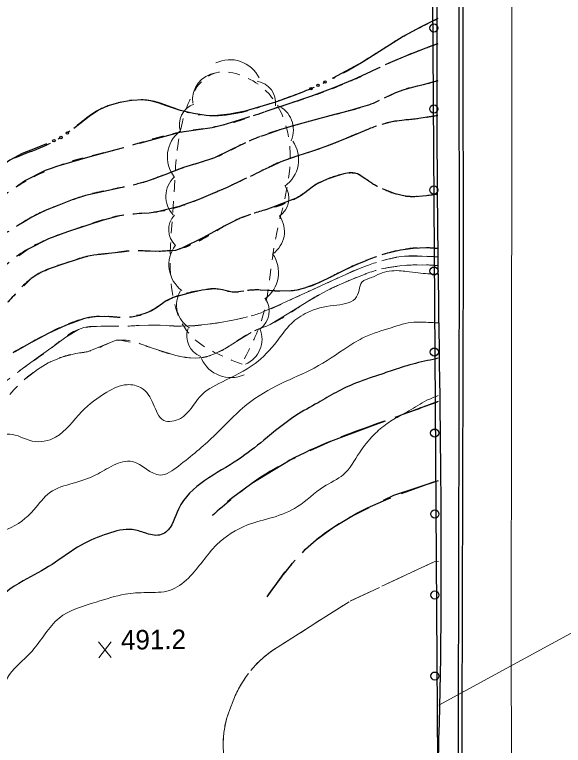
# Model space of a CAD drawing. Extents: x 2362213 to 2366494, y 6968794 to 6978110.
# Drawn here: x 2364260.3 to 2364395.9, y 6970244.9 to 6970425.3 of the extents above; entities that cross this region are included whole.
import ezdxf

# ---------------------------------------------------------------- set-up
doc = ezdxf.new("R2010")
doc.units = 0
doc.header["$LTSCALE"] = 1.9
for name, pattern in [('DASH_DOUBLE_DOT', [9.2, 5, -1.2, 0.3, -1.2, 0.3, -1.2]), ('LONG_DASHED', [7.5, 6, -1.5]), ('MEDIUM_DASHED', [4.5, 3, -1.5]), ('SHORT_DASHED', [2.7, 1.5, -1.2])]:
    doc.linetypes.add(name, pattern=pattern)
for name, color, linetype, lineweight in [('2', 7, 'Continuous', 25), ('25', 7, 'Continuous', 25), ('29', 7, 'Continuous', 13), ('3', 7, 'Continuous', 25), ('31', 7, 'Continuous', 25), ('32', 7, 'Continuous', 25), ('35', 7, 'Continuous', 13), ('36', 7, 'Continuous', 13), ('4', 7, 'Continuous', 25), ('62', 7, 'Continuous', 13), ('8', 7, 'Continuous', 13), ('9', 7, 'Continuous', 13)]:
    doc.layers.add(name, color=color, linetype=linetype, lineweight=lineweight)

msp = doc.modelspace()

# ---------------------------------------------------------------- linework, layer by layer
at = {"layer": '2'}
msp.add_line((2364369.912, 6970250.572), (2364369.913, 6970250.559), dxfattribs=at)
for points in [[(2364369.913, 6970250.559), (2364370.193, 6970367.087), (2364369.986, 6970514.833), (2364369.855, 6970701.89), (2364369.323, 6970871.152), (2364368.954, 6970929.733), (2364368.956, 6970929.692)], [(2364370.872, 6970250.558), (2364371.153, 6970367.086), (2364370.946, 6970514.832), (2364370.815, 6970701.889), (2364370.282, 6970871.162), (2364369.914, 6970929.742), (2364369.914, 6970929.741)]]:
    msp.add_lwpolyline(points, dxfattribs=at)
for centre, radius, start, end in [((2348841.903, 6970149.815), 15528.336, 0.23277, 0.37177), ((2348832.824, 6970339.444), 15538.302, 359.53334, 359.67224)]:
    msp.add_arc(centre, radius, start, end, dxfattribs=at)
at = {"layer": '25'}
for points in [[(2364364.847, 6970424.35), (2364360.517, 6970422.208), (2364356.278, 6970419.897), (2364351.328, 6970416.799), (2364346.378, 6970413.692), (2364339.98, 6970410.201), (2364338.746, 6970409.599)], [(2364331.637, 6970406.291), (2364329.107, 6970405.267), (2364324.692, 6970403.755), (2364317.212, 6970401.535), (2364313.449, 6970400.759), (2364309.673, 6970400.343), (2364307.582, 6970400.393), (2364304.427, 6970400.903), (2364301.291, 6970401.642), (2364297.578, 6970402.907), (2364295.751, 6970403.57), (2364293.886, 6970404.062), (2364292.004, 6970404.274), (2364289.135, 6970404.157), (2364286.28, 6970403.659), (2364283.667, 6970402.925), (2364282.402, 6970402.422), (2364281.167, 6970401.821), (2364278.674, 6970400.198), (2364275.219, 6970397.444), (2364274.931, 6970397.241)], [(2364268.106, 6970393.466), (2364265.307, 6970392.289), (2364262.099, 6970391.009), (2364259.085, 6970389.39), (2364250.531, 6970383.398), (2364242.191, 6970377.129), (2364233.253, 6970369.623), (2364224.051, 6970362.335), (2364220.43, 6970360.25), (2364218.926, 6970359.646)]]:
    msp.add_lwpolyline(points, dxfattribs=at)
for centre in [(2364335.221, 6970407.892), (2364336.949, 6970408.73), (2364333.494, 6970407.054), (2364271.724, 6970395.004), (2364273.3, 6970396.102), (2364269.965, 6970394.24)]:
    msp.add_circle(centre, 0.3, dxfattribs=at)
at = {"layer": '25', "linetype": 'DASH_DOUBLE_DOT'}
msp.add_spline([(2364364.847, 6970424.35), (2364356.278, 6970419.897), (2364346.378, 6970413.692), (2364333.4, 6970407.008), (2364324.692, 6970403.755), (2364309.673, 6970400.343), (2364301.291, 6970401.642), (2364293.886, 6970404.062), (2364286.28, 6970403.659), (2364281.167, 6970401.821), (2364271.632, 6970394.94), (2364259.085, 6970389.39), (2364242.191, 6970377.129), (2364224.051, 6970362.335), (2364208.66, 6970356.078), (2364195, 6970352.758)], degree=3, dxfattribs=at)
at = {"layer": '29'}
for centre, radius, start, end in [((2364313.464, 6970406.214), 7.997, 25.86205, 115.86205), ((2364310.899, 6970404.35), 6.668, 97.66191, 187.66191), ((2364319.431, 6970403.598), 5.329, 351.41371, 81.41371), ((2364306.313, 6970398.206), 5.329, 108.91941, 198.91941), ((2364322.487, 6970396.867), 6.668, 336.53524, 66.53524), ((2364306.016, 6970390.241), 7.997, 128.05769, 218.05769), ((2364322.439, 6970389.537), 7.997, 304.77131, 34.77131), ((2364304.312, 6970380.451), 6.668, 133.30247, 223.30247), ((2364322.718, 6970379.984), 5.329, 304.71158, 34.71158), ((2364303.66, 6970372.231), 5.329, 137.16086, 227.16086), ((2364320.271, 6970371.783), 6.668, 304.71158, 34.71158), ((2364306.396, 6970363.591), 7.997, 143.11461, 233.11461), ((2364317.488, 6970361.674), 7.997, 305.3686, 35.3686), ((2364306.943, 6970353.678), 6.668, 148.95248, 238.95248), ((2364317.843, 6970352.137), 5.329, 305.18192, 35.18192), ((2364308.128, 6970345.947), 5.329, 159.55382, 249.55382), ((2364314.725, 6970345.178), 6.668, 292.65251, 22.65251), ((2364313.708, 6970343.713), 7.997, 204.51246, 294.51246)]:
    msp.add_arc(centre, radius, start, end, dxfattribs=at)
at = {"layer": '29', "linetype": 'SHORT_DASHED'}
msp.add_spline([(2364316.457, 6970339.004), (2364304.052, 6970345.836), (2364299.605, 6970380.155), (2364300.565, 6970392.825), (2364310.032, 6970410.956), (2364321.135, 6970407.612), (2364328.361, 6970390.12), (2364324.524, 6970368.912), (2364321.255, 6970349.84), (2364316.573, 6970339.455)], degree=3, dxfattribs=at)
at = {"layer": '3'}
msp.add_line((2364309.876, 6970302.35), (2364309.132, 6970301.692), dxfattribs=at)
for points in [[(2364364.938, 6970329.785), (2364361.15, 6970328.399), (2364357.363, 6970327.003), (2364355.549, 6970326.336)], [(2364351.792, 6970324.95), (2364347.827, 6970323.492), (2364338.289, 6970319.971), (2364333.201, 6970317.612)], [(2364329.577, 6970315.928), (2364328.323, 6970315.346), (2364318.877, 6970309.565), (2364313.823, 6970305.847), (2364312.871, 6970305.008)], [(2364351.429, 6970305.425), (2364353.986, 6970306.69), (2364364.983, 6970310.345)], [(2364331.401, 6970292.484), (2364332.173, 6970293.331), (2364334.8, 6970295.697), (2364339.021, 6970298.797), (2364343.566, 6970301.54), (2364347.846, 6970303.651)], [(2364322.645, 6970281.58), (2364327.057, 6970287.701), (2364328.709, 6970289.518)]]:
    msp.add_lwpolyline(points, dxfattribs=at)
at = {"layer": '3', "linetype": 'LONG_DASHED'}
for points in [[(2364364.938, 6970329.785), (2364357.363, 6970327.003), (2364338.289, 6970319.971), (2364318.877, 6970309.565), (2364309.132, 6970301.692)], [(2364322.645, 6970281.58), (2364332.173, 6970293.331), (2364343.566, 6970301.54), (2364364.983, 6970310.345)]]:
    msp.add_spline(points, degree=3, dxfattribs=at)
at = {"layer": '31', "lineweight": 13}
for p, q in [((2364284.125, 6970266.593), (2364281.009, 6970270.443)), ((2364281.046, 6970266.563), (2364284.088, 6970270.473))]:
    msp.add_line(p, q, dxfattribs=at)
at = {"layer": '31'}
msp.add_spline([(2364364.916, 6970340.535), (2364363.708, 6970340.224), (2364360.793, 6970339.586), (2364355.098, 6970337.982), (2364350.983, 6970336.593), (2364344.743, 6970334.403), (2364339.684, 6970332.075), (2364335.238, 6970329.512), (2364329.728, 6970326.32), (2364321.827, 6970320.254), (2364315.571, 6970315.494), (2364307.24, 6970310.284), (2364300.728, 6970303.272), (2364297.611, 6970297.563), (2364296.087, 6970296.848), (2364292.482, 6970297.354), (2364289.344, 6970298.194), (2364283.244, 6970297.156), (2364276.711, 6970294.353), (2364269.505, 6970289.585), (2364262.404, 6970285.546), (2364254.518, 6970278.891), (2364252.946, 6970276.856), (2364250.196, 6970275.81), (2364245.104, 6970269.681), (2364243.153, 6970266.583), (2364239.68, 6970265.898), (2364238.01, 6970263.732), (2364238.482, 6970262.497)], degree=3, dxfattribs=at)
at = {"layer": '32'}
for points in [[(2364364.846, 6970418.158), (2364363.361, 6970417.614), (2364361.886, 6970417.06), (2364357.223, 6970415.206), (2364352.601, 6970413.271), (2364351.865, 6970412.924)], [(2364348.242, 6970411.23), (2364344.1, 6970409.28), (2364338.919, 6970407.141), (2364333.658, 6970405.191), (2364328.005, 6970403.277), (2364322.344, 6970401.404), (2364322.085, 6970401.321)], [(2364364.843, 6970409.028), (2364363.047, 6970408.501), (2364361.252, 6970407.994), (2364358.848, 6970407.401), (2364356.443, 6970406.798), (2364354.371, 6970406.018), (2364351.563, 6970404.721)], [(2364347.919, 6970403.086), (2364345.656, 6970402.365), (2364342.963, 6970401.59), (2364338.114, 6970400.314), (2364333.266, 6970399.038), (2364329.656, 6970398.022), (2364326.057, 6970396.958), (2364321.86, 6970395.518), (2364321.063, 6970395.21)], [(2364318.286, 6970400.075), (2364317.039, 6970399.673), (2364311.715, 6970398.011), (2364309.08, 6970397.426), (2364301.032, 6970396.22), (2364293.79, 6970394.271), (2364291.106, 6970393.545)], [(2364364.846, 6970400.398), (2364362.228, 6970399.983), (2364359.612, 6970399.589), (2364356.545, 6970399.239), (2364353.489, 6970398.86), (2364351.035, 6970398.216)], [(2364347.268, 6970396.88), (2364343.623, 6970395.365), (2364339.737, 6970393.768), (2364336.936, 6970392.721), (2364334.126, 6970391.695), (2364330.038, 6970390.416), (2364326.022, 6970388.987), (2364323.812, 6970387.956), (2364321.602, 6970386.905), (2364321.204, 6970386.721)], [(2364317.356, 6970393.715), (2364313.713, 6970391.92), (2364309.661, 6970390.001), (2364305.833, 6970388.765), (2364301.985, 6970387.558), (2364297.421, 6970385.785), (2364292.816, 6970384.151), (2364291.25, 6970383.746)], [(2364287.246, 6970392.488), (2364286.548, 6970392.301), (2364278.859, 6970390.188), (2364271.188, 6970388.035), (2364267.809, 6970386.843), (2364262.992, 6970384.387), (2364261.055, 6970383.068)], [(2364347.688, 6970384.273), (2364346.652, 6970384.983), (2364345.826, 6970385.556), (2364344.961, 6970386.027), (2364344.38, 6970386.222), (2364343.309, 6970386.322), (2364341.63, 6970386.056), (2364340.005, 6970385.57), (2364337.473, 6970384.676), (2364335.024, 6970383.553), (2364333.761, 6970382.721), (2364331.975, 6970381.314), (2364331.051, 6970380.665), (2364330.066, 6970380.135), (2364326.241, 6970378.589), (2364322.375, 6970377.173), (2364322.365, 6970377.173)], [(2364317.599, 6970384.997), (2364317.181, 6970384.793), (2364312.751, 6970382.691), (2364309.275, 6970381.147), (2364305.749, 6970379.694), (2364300.896, 6970377.998), (2364295.927, 6970376.691), (2364293.51, 6970376.337), (2364291.221, 6970376.215)], [(2364287.359, 6970382.809), (2364286.84, 6970382.684), (2364282.309, 6970381.701), (2364277.789, 6970380.668), (2364274.479, 6970379.596), (2364271.231, 6970378.315), (2364267.813, 6970376.953), (2364264.509, 6970375.341), (2364262.222, 6970373.949), (2364261.208, 6970373.319)], [(2364364.83, 6970380.996), (2364362.013, 6970380.58), (2364359.185, 6970380.383), (2364357.975, 6970380.381), (2364356.754, 6970380.499), (2364354.308, 6970381.066), (2364351.96, 6970381.954), (2364351.186, 6970382.337)], [(2364287.245, 6970375.797), (2364286.216, 6970375.668), (2364282.137, 6970374.559), (2364278.09, 6970373.31), (2364273.334, 6970371.715), (2364268.64, 6970369.94), (2364263.624, 6970367.422), (2364261.269, 6970365.82)], [(2364318.555, 6970375.956), (2364316.034, 6970375.051), (2364314.033, 6970374.082), (2364312.062, 6970373.074), (2364306.908, 6970370.334), (2364301.604, 6970367.654), (2364300.019, 6970367.139), (2364297.551, 6970366.895), (2364295.071, 6970366.871), (2364292.6, 6970366.978)], [(2364288.61, 6970366.95), (2364286.652, 6970366.711), (2364284.255, 6970366.408), (2364282.057, 6970366.178), (2364279.85, 6970365.937), (2364278.023, 6970365.599), (2364272.678, 6970363.918), (2364268.332, 6970362.407), (2364266.271, 6970361.437), (2364264.363, 6970360.169), (2364262.52, 6970358.401)], [(2364364.848, 6970367.576), (2364363.356, 6970367.712), (2364361.875, 6970367.758), (2364358.746, 6970367.628), (2364355.63, 6970367.208), (2364351.859, 6970366.312), (2364351.041, 6970366.034)], [(2364347.285, 6970364.669), (2364344.974, 6970363.697), (2364341.777, 6970362.256), (2364338.631, 6970360.696), (2364335.466, 6970359.136), (2364331.869, 6970357.761), (2364330.003, 6970357.304), (2364328.116, 6970357.056), (2364324.555, 6970357.162), (2364320.994, 6970357.338), (2364320.854, 6970357.337)], [(2364316.865, 6970357.069), (2364316.166, 6970356.962), (2364314.978, 6970356.781), (2364313.657, 6970356.868), (2364311.662, 6970357.349), (2364310.67, 6970357.55), (2364309.679, 6970357.62), (2364308.16, 6970357.506), (2364306.643, 6970357.271), (2364303.031, 6970356.497), (2364299.48, 6970355.473), (2364297.737, 6970354.637), (2364295.323, 6970352.973), (2364294.08, 6970352.191), (2364292.726, 6970351.598), (2364291.13, 6970351.153), (2364290.351, 6970351.016)], [(2364286.385, 6970350.578), (2364286.285, 6970350.567), (2364284.324, 6970350.708), (2364282.363, 6970350.84), (2364279.835, 6970350.706), (2364278.577, 6970350.524), (2364277.319, 6970350.212), (2364272.804, 6970348.589), (2364268.523, 6970346.588), (2364266.423, 6970345.488), (2364264.344, 6970344.358), (2364260.504, 6970342.161), (2364260.345, 6970342.07)]]:
    msp.add_lwpolyline(points, dxfattribs=at)
at = {"layer": '32', "linetype": 'SHORT_DASHED'}
for points in [[(2364364.846, 6970418.158), (2364361.886, 6970417.06), (2364352.601, 6970413.271), (2364344.1, 6970409.28), (2364333.658, 6970405.191), (2364322.344, 6970401.404), (2364311.715, 6970398.011), (2364301.032, 6970396.22), (2364286.548, 6970392.301), (2364271.188, 6970388.035), (2364258.521, 6970381.334), (2364245.947, 6970371.184), (2364239.365, 6970366.191), (2364225.916, 6970358.643), (2364217.01, 6970353.978), (2364202.526, 6970348.039)], [(2364364.843, 6970409.028), (2364361.252, 6970407.994), (2364356.443, 6970406.798), (2364348.318, 6970403.22), (2364342.963, 6970401.59), (2364333.266, 6970399.038), (2364326.057, 6970396.958), (2364317.734, 6970393.899), (2364309.661, 6970390.001), (2364301.985, 6970387.558), (2364292.816, 6970384.151), (2364286.84, 6970382.684), (2364277.789, 6970380.668), (2364271.231, 6970378.315), (2364264.509, 6970375.341), (2364259.955, 6970372.537), (2364255.123, 6970369.681), (2364250.295, 6970366.155), (2364248.152, 6970364.425), (2364245.292, 6970361.247), (2364242.781, 6970358.163), (2364237.11, 6970356.199), (2364232.291, 6970355.093)], [(2364364.846, 6970400.398), (2364359.612, 6970399.589), (2364353.489, 6970398.86), (2364347.507, 6970396.982), (2364339.737, 6970393.768), (2364334.126, 6970391.695), (2364326.022, 6970388.987), (2364321.602, 6970386.905), (2364312.751, 6970382.691), (2364305.749, 6970379.694), (2364295.927, 6970376.691), (2364286.216, 6970375.668), (2364278.09, 6970373.31), (2364268.64, 6970369.94), (2364258.974, 6970364.258), (2364252.648, 6970358.517), (2364248.675, 6970355.709)], [(2364364.83, 6970380.996), (2364359.185, 6970380.383), (2364356.754, 6970380.499), (2364351.96, 6970381.954), (2364348.302, 6970383.859), (2364344.961, 6970386.027), (2364340.005, 6970385.57), (2364335.024, 6970383.553), (2364330.066, 6970380.135), (2364322.375, 6970377.173), (2364316.034, 6970375.051), (2364312.062, 6970373.074), (2364301.604, 6970367.654), (2364295.071, 6970366.871), (2364289.049, 6970367.004), (2364284.255, 6970366.408), (2364279.85, 6970365.937), (2364272.678, 6970363.918), (2364264.363, 6970360.169), (2364258.637, 6970354.444), (2364251.944, 6970348.45), (2364245.525, 6970338.888), (2364243.364, 6970334.818), (2364238.212, 6970332.839), (2364230.715, 6970332.507), (2364221.484, 6970331.538), (2364213.708, 6970331.074), (2364206.141, 6970331.752), (2364197.681, 6970333.823)], [(2364364.848, 6970367.576), (2364361.875, 6970367.758), (2364355.63, 6970367.208), (2364348.211, 6970365.057), (2364341.777, 6970362.256), (2364335.466, 6970359.136), (2364328.116, 6970357.056), (2364320.994, 6970357.338), (2364317.364, 6970357.143), (2364314.978, 6970356.781), (2364309.679, 6970357.62), (2364306.643, 6970357.271), (2364299.48, 6970355.473), (2364292.726, 6970351.598), (2364286.285, 6970350.567), (2364282.363, 6970350.84), (2364277.319, 6970350.212), (2364268.523, 6970346.588), (2364264.344, 6970344.358), (2364256.697, 6970339.895), (2364249.127, 6970333.432), (2364244.461, 6970319.387), (2364241.848, 6970311.192), (2364238.032, 6970310.766), (2364231.618, 6970311.275), (2364224.298, 6970312.255), (2364217.804, 6970313.663), (2364212.629, 6970314.124), (2364205.732, 6970314.848), (2364194.373, 6970316.77), (2364179.745, 6970317.591)]]:
    msp.add_spline(points, degree=3, dxfattribs=at)
at = {"layer": '35'}
for points in [[(2364364.869, 6970361.176), (2364359.954, 6970361.559), (2364357.181, 6970361.893), (2364355.279, 6970362.105), (2364350.507, 6970361.369), (2364348.396, 6970360.399), (2364346.086, 6970359.317), (2364345.395, 6970357.32), (2364344.385, 6970355.202), (2364339.1, 6970353.54), (2364332.596, 6970351.778), (2364328.642, 6970349.06), (2364325.045, 6970344.656), (2364319.665, 6970339.174), (2364311.429, 6970334.616), (2364306.043, 6970331.004), (2364301.225, 6970325.638), (2364297.098, 6970325.159), (2364294.529, 6970329.245), (2364291.561, 6970333.177), (2364288.074, 6970333.963), (2364283.071, 6970332.115), (2364276.847, 6970327.316), (2364270.386, 6970320.994), (2364264.575, 6970320.049), (2364259.068, 6970321.777), (2364252.806, 6970317.847), (2364249.725, 6970305.317), (2364244.346, 6970297.805), (2364233.011, 6970296.287), (2364222.955, 6970294.682), (2364211.465, 6970293.652), (2364200.277, 6970293.315), (2364191.374, 6970294.591), (2364180.631, 6970295.909)], [(2364364.893, 6970349.256), (2364362.421, 6970349.352), (2364358.94, 6970349.399), (2364353.293, 6970348.035), (2364346.666, 6970345.682), (2364342.618, 6970343.323), (2364334.287, 6970338.074), (2364326.104, 6970334.246), (2364317.672, 6970329.075), (2364309.426, 6970321.206), (2364300.746, 6970313.883), (2364296.247, 6970311.64), (2364289.365, 6970314.975), (2364284.673, 6970314.06), (2364280.337, 6970311.669), (2364274.695, 6970309.634), (2364268.976, 6970307.33), (2364265.027, 6970303.043), (2364258.533, 6970298.32), (2364254.035, 6970297.018), (2364249.354, 6970294.883), (2364244.948, 6970291.271), (2364241.093, 6970286.533), (2364238.443, 6970282.378), (2364234.948, 6970279.815), (2364230.3, 6970282.591), (2364224.36, 6970285.753), (2364217.545, 6970284.15), (2364212.757, 6970278.634), (2364208.692, 6970274.915), (2364198.732, 6970273.87), (2364192.503, 6970276.831), (2364184.268, 6970280.492)], [(2364364.934, 6970331.275), (2364362.144, 6970330.109), (2364357.699, 6970327.476), (2364355.669, 6970326.367), (2364352.328, 6970324.385), (2364349.035, 6970321.583), (2364345.467, 6970317.179), (2364341.517, 6970311.781), (2364336.606, 6970308.744), (2364330.172, 6970303.853), (2364324.058, 6970301.205), (2364317.825, 6970299.335), (2364310.241, 6970294.473), (2364303.2, 6970286.224), (2364298.569, 6970283.181), (2364292.843, 6970282.646), (2364287.566, 6970282.236), (2364280.435, 6970280.298), (2364271.242, 6970276.33), (2364264.589, 6970268.207), (2364258.256, 6970261.216), (2364256.007, 6970252.664), (2364250.581, 6970244.802)]]:
    msp.add_spline(points, degree=3, dxfattribs=at)
at = {"layer": '36'}
for points in [[(2364364.857, 6970365.546), (2364362.915, 6970365.637), (2364360.975, 6970365.699), (2364358.794, 6970365.728), (2364356.615, 6970365.677), (2364354.557, 6970365.418), (2364352.522, 6970364.948), (2364350.987, 6970364.524)], [(2364347.178, 6970363.298), (2364345.514, 6970362.682), (2364341.4, 6970360.852), (2364337.308, 6970358.993), (2364333.444, 6970357.236), (2364329.591, 6970355.47), (2364325.28, 6970353.519), (2364321.595, 6970351.923)], [(2364364.858, 6970363.386), (2364363.006, 6970363.518), (2364361.145, 6970363.571), (2364358.286, 6970363.493), (2364355.418, 6970363.276), (2364353.13, 6970363.004), (2364350.935, 6970362.543)], [(2364347.127, 6970361.337), (2364343.5, 6970359.932), (2364341.019, 6970358.899), (2364338.589, 6970357.765), (2364335.545, 6970356.136), (2364332.551, 6970354.428), (2364327.987, 6970351.634), (2364323.414, 6970348.861), (2364322.379, 6970348.371)], [(2364317.796, 6970350.707), (2364315.022, 6970350.061), (2364311.538, 6970349.397), (2364308.023, 6970348.874), (2364304.796, 6970348.553), (2364301.568, 6970348.403), (2364297.705, 6970348.556), (2364293.844, 6970348.699), (2364290.675, 6970348.559), (2364290.005, 6970348.522)], [(2364286.006, 6970348.394), (2364284.526, 6970348.38), (2364281.546, 6970348.392), (2364278.737, 6970348.335), (2364277.359, 6970348.112), (2364276.014, 6970347.609), (2364272.901, 6970345.679), (2364270.021, 6970343.572), (2364266.068, 6970340.724), (2364262.135, 6970337.857), (2364261.401, 6970337.29)], [(2364318.693, 6970346.836), (2364315.779, 6970345.068), (2364312.588, 6970343.067), (2364309.632, 6970341.599), (2364308.107, 6970341.034), (2364306.551, 6970340.64), (2364304.952, 6970340.484), (2364302.501, 6970340.671), (2364300.096, 6970341.208), (2364297.207, 6970342.081), (2364294.308, 6970342.973), (2364292.664, 6970343.448)], [(2364288.794, 6970344.431), (2364286.329, 6970344.927), (2364285.329, 6970344.918), (2364278.476, 6970342.162), (2364276.958, 6970341.928), (2364275.43, 6970341.683), (2364271.948, 6970340.74), (2364268.592, 6970339.338), (2364265.897, 6970337.752), (2364263.038, 6970335.495)]]:
    msp.add_lwpolyline(points, dxfattribs=at)
at = {"layer": '36', "linetype": 'SHORT_DASHED'}
for points in [[(2364364.857, 6970365.546), (2364360.975, 6970365.699), (2364356.615, 6970365.677), (2364352.522, 6970364.948), (2364345.514, 6970362.682), (2364337.308, 6970358.993), (2364329.591, 6970355.47), (2364320.928, 6970351.627), (2364315.022, 6970350.061), (2364308.023, 6970348.874), (2364301.568, 6970348.403), (2364293.844, 6970348.699), (2364287.496, 6970348.399), (2364281.546, 6970348.392), (2364276.014, 6970347.609), (2364270.021, 6970343.572), (2364262.135, 6970337.857), (2364254.831, 6970332.086), (2364248.161, 6970324.593), (2364244.647, 6970314.509), (2364240.441, 6970307.759), (2364233.628, 6970306.014), (2364223.435, 6970307.307), (2364210.493, 6970309.603), (2364199.871, 6970310.772), (2364190.713, 6970311.505), (2364181.342, 6970312.626)], [(2364364.858, 6970363.386), (2364361.145, 6970363.571), (2364355.418, 6970363.276), (2364350.875, 6970362.533), (2364343.5, 6970359.932), (2364338.589, 6970357.765), (2364332.551, 6970354.428), (2364323.414, 6970348.861), (2364318.961, 6970346.998), (2364312.588, 6970343.067), (2364306.551, 6970340.64), (2364300.096, 6970341.208), (2364294.308, 6970342.973), (2364286.329, 6970344.927), (2364278.476, 6970342.162), (2364275.43, 6970341.683), (2364268.592, 6970339.338), (2364259.056, 6970331.526), (2364252.573, 6970322.345), (2364245.732, 6970308.688), (2364242.575, 6970303.129), (2364234.798, 6970300.815), (2364223.394, 6970302.156), (2364213.256, 6970303.97), (2364201.54, 6970306.668), (2364190.19, 6970307.619), (2364176.239, 6970309.816)]]:
    msp.add_spline(points, degree=3, dxfattribs=at)
at = {"layer": '4'}
msp.add_line((2364359.347, 6971077.993), (2364364.943, 6970212.75), dxfattribs=at)
for centre in [(2364363.864, 6970422.028), (2364363.85, 6970402.028), (2364363.836, 6970382.028), (2364363.888, 6970362.023), (2364363.97, 6970342.024), (2364364.053, 6970322.024), (2364364.102, 6970302.027), (2364364.109, 6970282.027), (2364364.116, 6970262.027)]:
    msp.add_circle(centre, 1, dxfattribs=at)
msp.add_spline([(2364358.277, 6970112.342), (2364361.924, 6970148.357), (2364363.973, 6970182.139), (2364363.141, 6970205.392), (2364364.236, 6970226.034), (2364365.123, 6970246.333), (2364364.832, 6970375.556), (2364364.876, 6970504.322), (2364364.587, 6970660.737), (2364364.458, 6970830.654), (2364364.317, 6970921.087), (2364363.346, 6970944.209), (2364361.189, 6970974.401), (2364360.625, 6971005.267), (2364359.468, 6971054.297), (2364359.925, 6971077.632)], degree=3, dxfattribs=at)
at = {"layer": '62'}
msp.add_spline([(2364383.348, 6970112.421), (2364382.992, 6970277.885), (2364383.14, 6970438.813), (2364382.733, 6970634.828), (2364382.506, 6970838.246), (2364381.952, 6970986.738), (2364381.794, 6971076.85)], degree=3, dxfattribs=at)
at = {"layer": '8'}
for p, q in [((2364359.483, 6970288.16), (2364352.235, 6970284.762)), ((2364350.424, 6970283.915), (2364343.176, 6970280.526)), ((2364341.475, 6970279.479), (2364334.726, 6970275.185)), ((2364333.036, 6970274.109), (2364326.287, 6970269.804))]:
    msp.add_line(p, q, dxfattribs=at)
at = {"layer": '8', "linetype": 'MEDIUM_DASHED'}
msp.add_lwpolyline([(2364365.024, 6970290.284), (2364363.923, 6970290.244), (2364342.907, 6970280.393), (2364324.25, 6970268.505)], dxfattribs=at)
at = {"layer": '8'}
for points in [[(2364365.024, 6970290.284), (2364363.923, 6970290.244), (2364361.295, 6970289.009)], [(2364324.598, 6970268.728), (2364324.25, 6970268.505), (2364323.862, 6970268.241), (2364323.485, 6970267.968), (2364323.117, 6970267.694), (2364322.74, 6970267.4), (2364322.373, 6970267.117), (2364322.016, 6970266.814), (2364321.659, 6970266.51), (2364321.311, 6970266.207), (2364320.974, 6970265.883), (2364320.628, 6970265.559), (2364320.301, 6970265.236), (2364319.974, 6970264.903), (2364319.646, 6970264.56), (2364319.339, 6970264.217), (2364319.033, 6970263.864), (2364318.726, 6970263.511), (2364318.657, 6970263.42)], [(2364317.432, 6970261.84), (2364317.304, 6970261.658), (2364317.047, 6970261.276), (2364316.791, 6970260.884), (2364316.535, 6970260.491), (2364316.298, 6970260.089), (2364316.062, 6970259.687), (2364315.826, 6970259.284), (2364315.61, 6970258.872), (2364315.394, 6970258.46), (2364315.188, 6970258.038), (2364314.982, 6970257.616), (2364314.796, 6970257.194), (2364314.61, 6970256.763), (2364314.424, 6970256.331), (2364314.258, 6970255.899), (2364314.092, 6970255.458), (2364313.937, 6970255.016), (2364313.888, 6970254.866), (2364313.829, 6970254.725)], [(2364313.097, 6970252.868), (2364312.99, 6970252.547), (2364312.854, 6970252.156), (2364312.738, 6970251.754), (2364312.631, 6970251.363), (2364312.525, 6970250.952), (2364312.419, 6970250.551), (2364312.333, 6970250.151), (2364312.247, 6970249.75), (2364312.171, 6970249.339), (2364312.105, 6970248.928), (2364312.038, 6970248.518), (2364311.982, 6970248.107), (2364311.926, 6970247.697), (2364311.89, 6970247.286), (2364311.854, 6970246.876), (2364311.828, 6970246.456), (2364311.812, 6970246.045), (2364311.796, 6970245.635), (2364311.79, 6970245.215), (2364311.792, 6970245.015)]]:
    msp.add_lwpolyline(points, dxfattribs=at)
at = {"layer": '8', "linetype": 'MEDIUM_DASHED'}
for centre, radius, start, end in [((2364339.247, 6970246.358), 26.747, 124.10579, 161.45398), ((2364335.536, 6970245.104), 23.746, 155.72745, 201.78572)]:
    msp.add_arc(centre, radius, start, end, dxfattribs=at)
at = {"layer": '9'}
msp.add_line((2364399.444, 6970273.501), (2364365.102, 6970254.803), dxfattribs=at)

# ---------------------------------------------------------------- texts
at = {"layer": '31'}
msp.add_text('491.2', height=4.8, rotation=0.546, dxfattribs=at).set_placement((2364286.566, 6970268.556))

doc.saveas('drawing.dxf')
